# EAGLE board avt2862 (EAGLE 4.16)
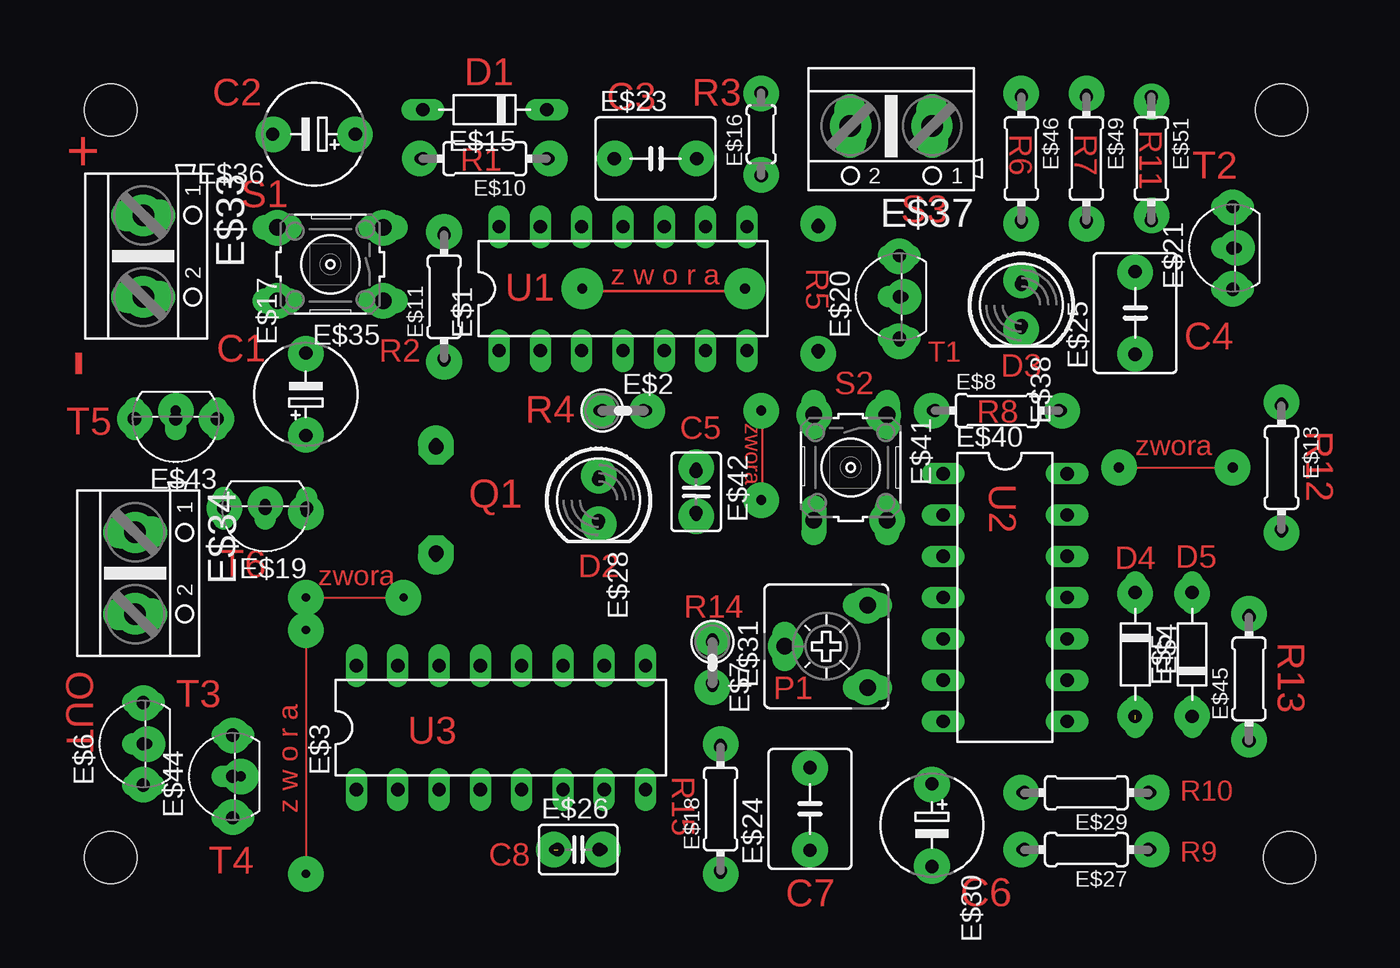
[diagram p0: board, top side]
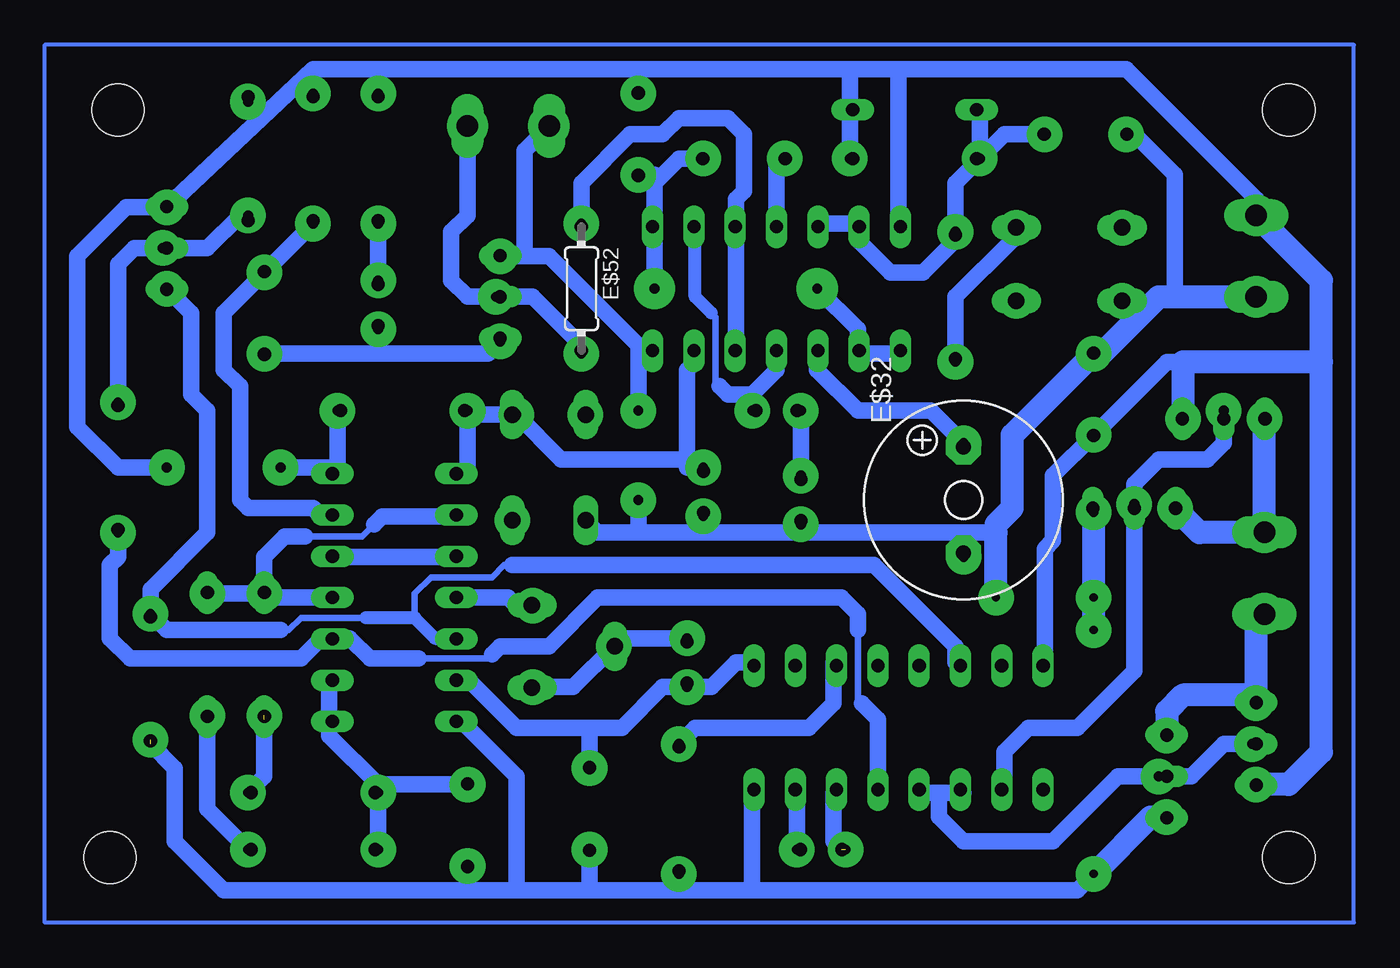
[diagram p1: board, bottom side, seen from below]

No outline drawn. Coordinates in mm, seen from the top.
Copper layers (1*16): Top 0.035mm / dielectric 1.5mm / Bottom 0.035mm
Design rules "default": minimum track width 10mil, minimum drill 24mil, track to track 8mil, track to pad 8mil, pad to pad 8mil, via to via 8mil, smd to smd 8mil, copper to edge 40mil, drill to drill 8mil, minimum pad ring 10mil, minimum via ring 8mil, stop-mask expansion 4mil, vias tented up to drill 0mil, thermal gap 10mil
Holes 3.2 mm at 0,54 0,8 72.5,8 72,54

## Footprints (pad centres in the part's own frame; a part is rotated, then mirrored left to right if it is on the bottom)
DIL14 = drill 0.813 long: 1 -7.62,-3.81; 2 -5.08,-3.81; 3 -2.54,-3.81; 4 0,-3.81; 5 2.54,-3.81; 6 5.08,-3.81; 7 7.62,-3.81; 8 7.62,3.81; 9 5.08,3.81; 10 2.54,3.81; 11 0,3.81; 12 -2.54,3.81; 13 -5.08,3.81; 14 -7.62,3.81
0207/2V = drill 0.813 octagon: 1 -1.27,0; 2 1.27,0
DIL16 = drill 0.813 long: 1 -8.89,-3.81; 2 -6.35,-3.81; 3 -3.81,-3.81; 4 -1.27,-3.81; 5 1.27,-3.81; 6 3.81,-3.81; 7 6.35,-3.81; 8 8.89,-3.81; 9 8.89,3.81; 10 6.35,3.81; 11 3.81,3.81; 12 1.27,3.81; 13 -1.27,3.81; 14 -3.81,3.81; 15 -6.35,3.81; 16 -8.89,3.81
D-7.5 = drill 0.813 long: A 3.81,0; C -3.81,0
TO92- = drill 0.813 long: 1 2.54,0; 2 0,0; 3 -2.54,0
0204/7 = drill 0.813 octagon: 1 -3.81,0; 2 3.81,0
0204/5 = drill 0.813 octagon: 1 -2.54,0; 2 2.54,0
E5-6 = drill 0.813 pad 1.905 round: + -2.54,0 | drill 0.813 pad 1.905 octagon: - 2.54,0
C050-050X075 = drill 0.813 octagon: 1 -2.54,0; 2 2.54,0
C025-030X050 = drill 0.813 octagon: 1 -1.27,0; 2 1.27,0
LED5MM = drill 0.813 octagon: A -1.27,0; K 1.27,0
CA6V = drill 1.016 long: A -2.54,-2.54; E 2.54,-2.54; S 0,2.54
F/QMX = drill 0.914 pad 2.159 octagon: + 3.251,0; - -3.251,0
AK500/2 = drill 1.321 long: 1 -2.515,0; 2 2.515,0
B3F-10XX = drill 1.016 long: 1 -3.251,2.261; 2 3.251,2.261; 3 -3.251,-2.261; 4 3.251,-2.261

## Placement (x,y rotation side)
E$1  [DIL14]  31.5,43 0 top
E$2  [0207/2V]  31.5,35.5 0 top
E$3  [DIL16]  24,16 0 top
E$4  [D-7.5]  63,20.5 270 top
E$5  [D-7.5]  66.5,20.5 90 top
E$6  [TO92-]  2,15 90 top
E$7  [0207/2V]  37,20 270 top
E$8  [0204/7]  54.5,35.5 0 top
E$10  [0204/7]  23,51 180 top
E$11  [0204/7]  20.5,42.5 90 top
E$13  [0204/7]  72,32 270 top
E$15  [D-7.5]  23,54 180 top
E$16  [0204/5]  40,52.5 90 top
E$17  [E5-6]  12,36.5 90 top
E$18  [0204/7]  37.5,11 90 top
E$19  [TO92-]  9.5,29.5 180 top
E$20  [TO92-]  48.5,42.5 90 top
E$21  [TO92-]  69,45.5 90 top
E$23  [C050-050X075]  33.5,51 0 top
E$24  [C050-050X075]  43,11 90 top
E$25  [C050-050X075]  63,41.5 90 top
E$26  [C025-030X050]  28.75,8.5 0 top
E$27  [0204/7]  60,8.5 180 top
E$28  [LED5MM]  30,30 270 top
E$29  [0204/7]  60,12 180 top
E$30  [E5-6]  50.5,10 270 top
E$31  [CA6V]  44,21 90 top
E$32  [F/QMX]  20,30 90 bottom
E$33  [AK500/2]  2,45 270 top
E$34  [AK500/2]  1.5,25.5 270 top
E$35  [B3F-10XX]  13.5,44.5 180 top
E$36  [E5-6]  12.5,52.5 180 top
E$37  [AK500/2]  48,53 180 top
E$38  [LED5MM]  56,42 270 top
E$40  [DIL14]  55,24 270 top
E$41  [B3F-10XX]  45.5,32 270 top
E$42  [C025-030X050]  36,30.5 270 top
E$43  [TO92-]  4,35 180 top
E$44  [TO92-]  7.5,13 90 top
E$45  [0204/7]  70,19 90 top
E$46  [0204/7]  56,51 270 top
E$49  [0204/7]  60,51 270 top
E$51  [0204/7]  64,51 270 top
E$52  [0204/7]  43.5,43 270 bottom

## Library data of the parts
E$1 E$3 E$40 = 40xx
E$2 E$7 E$8 E$10 E$11 E$13 E$16-E$18 E$23-E$27 E$29 E$30 E$36 E$42 E$45 E$46 E$49 E$51 E$52 = rcl
E$4 E$5 E$15 = diode
E$6 E$19-E$21 E$43 E$44 = transistor-npn
E$28 E$38 = led
E$31 = pot
E$32 = buzzer
E$33 E$34 E$37 = con-ptr500
E$35 E$41 = switch-omron

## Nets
S$79: E$19.2
S$95: E$6.2

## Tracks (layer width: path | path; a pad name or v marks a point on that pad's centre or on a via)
S$1
  Bottom 0.254: -4,4 76.5,4 76.5,58 -4,58 -4,4
S$2
  Bottom 1.422: 9.5,41.5 10,42
S$3  (via drill 0.6 pad 2.18)
  Bottom 1.016: v30,31.5 v30,35.5
S$4  (via drill 0.6 pad 2.18)
  Bottom 1.016: 17,47 17,46 20.5,42.5 v20.5,38.5
S$5
  Bottom 0.813: 36.5,47 36.5,42.5 35.5,41.5
S$6
  Bottom 1.016: 24,39 26.5,39
S$7
  Bottom 1.016: 59.5,21.5 57.75,21.5 56.5,20.25 53.5,20.25
S$8  (via drill 0.6 pad 2.18)
  other vias: 10.25,46.75
S$9  (via drill 0.6 pad 2.18)
  Bottom 1.016: 29,39 29,38 26.5,35.5 22,35.5 v20,33.5
S$10
  Bottom 1.016: 24,47 24,50.5
S$11  (via drill 0.6 pad 2.54)
  Bottom 1.016: 26.5,39.25 26.5,40.5 v29,43
S$12  (via drill 0.6 pad 2.18)
  Bottom 1.016: 31.5,47 31.5,50.5 v31,51
S$13  (via drill 0.6 pad 2.18)
  Bottom 1.016: 29,47 26.5,47 26.5,46 24.5,44 22.5,44 20.5,46 v20.5,46.5 20.5,49.5 v19,51 | v19,51 19,54 | v15,52.5 17.5,52.5 v19,51
S$14
  Bottom 0.406: 35.25,37 35.25,41.25
S$15  (via drill 0.6 pad 2.18, 0.6 pad 2.54)
  Bottom 1.016: v50.5,53 50.5,47.5 51.5,46.5 51.5,43.5 50.5,42.5 v48.75,42.5 46.5,42.5 43.5,39.5 v43.5,39
S$16  (via drill 0.6 pad 2.18)
  Bottom 1.016: 31.5,39 31.5,38 33,36.5 | 33,36.5 34.5,36.5 35,37 | v33,35.5 33,36.5
S$17  (via drill 0.6 pad 2.18)
  other vias: 20,26.5
S$18  (via drill 0.6 pad 2.18)
  Bottom 1.016: v43.5,47 43.5,49.5 40.5,52.5 38.5,52.5 37.5,53.5 34.5,53.5 33.5,52.5 33.5,49 34,48.5 34,39
S$19  (via drill 0.6 pad 2.18)
  Bottom 1.016: v56,43.5 v56,47
S$20  (via drill 0.6 pad 2.18)
  other vias: 8,13
S$21
  Bottom 1.016: 51,26.5 59,26.5
S$22
  Bottom 1.016: 20.5,20 20.5,21 25.5,26 47.75,26
S$23  (via drill 0.6 pad 2.18)
  Bottom 1.016: 58.5,29 59.5,29 60,29.5 64,29.5 64.5,30 64.5,37 65.5,38 65.5,41.5 v63,44 v60,47
S$24  (via drill 0.5 pad 2.18, 0.6 pad 2.18)  (1 unrouted)
  Bottom 1.016: 70,15 68.5,13.5 68.5,9 65.5,6 50.5,6 | 51,16.5 47.5,13 47.5,6 | 50.5,6 v50.5,7.5 | 47.5,6 50.5,6 | 43,6 v43,8.5 | 43,6 47.5,6 | 43,6 13,6 v12,7
  Bottom 1.422: v7.5,10.5 8.5,10.5 v12,7
  other vias: 70,15.25
S$25  (via drill 0.6 pad 2.18)
  Bottom 1.016: v37.5,15 36.5,16 35.5,16
S$26  (via drill 0.6 pad 2.18, 0.6 pad 2.54)
  Bottom 1.016: v45.5,53 47,51.5 47,45 | 47,45 45.5,45 40,39.5 | 47,45 v48.5,45 | 40,39.5 39,39.5 | v40,35.5 40,39.5
S$27  (via drill 0.6 pad 2.18)
  other vias: 10.25,42.25
S$28
  Bottom 0.406: 61.5,22 60.75,22.75 56.75,22.75
S$29  (via drill 0.6 pad 2.18)
  Bottom 1.016: 66.5,16.5 66.5,11 v64,8.5
S$30  (via drill 0.6 pad 2.18)
  Bottom 1.016: v56,8.5 56,12.5
S$31  (via drill 0.6 pad 2.18)  (1 unrouted)
  Bottom 1.016: 28,12 28,9 27.5,8.5
  other vias: 27.25,8.5
S$32  (via drill 0.6 pad 2.18)
  Bottom 1.016: v30.25,8.5 30.25,12.25
S$33  (via drill 0.6 pad 2.18)
  Bottom 1.016: 62,22 69,22 v70,23 70,24.5 66.5,28 66.5,35.5 67.5,36.5 67.5,41.5 v69,43
S$34
  Bottom 1.016: 35.5,16 29.5,16 28,17.5 28,20
S$35  (via drill 0.6 pad 2.18)
  Bottom 1.016: v50.5,12.5 56,12.5 59,15.5 59,19
S$36
  Bottom 1.016: 26.5,22 26.5,23 27.5,24 42.5,24 45.5,21 48.5,21 49,20.5
S$37  (via drill 0.6 pad 2.18)
  Bottom 1.016: 51,31.5 50.5,31.5 50.5,35.25 | 50.5,35.25 v50.5,35.5 | 50.5,35.25 v47.5,35.25 44.75,32.5 37.25,32.5 36.75,32 v36,32
S$38  (via drill 0.6 pad 2.18)
  Bottom 1.016: v37,21.5 41,21.5 v41.5,21 44,18.5 v46.5,18.5
S$39
  Bottom 1.016: 51,19 50.5,19 47.5,16 41,16 38.5,18.5 35.5,18.5 34,20 33,20
S$40  (via drill 0.6 pad 2.18)
  Bottom 1.016: 58.5,24 63,24 63,24.25 | 63,24.25 v66.5,24.25 | 60.5,27.75 61.75,27.75 63,26.5 63,24.25
S$41  (via drill 0.6 pad 2.18)
  Bottom 1.016: 56,39 v63,39 | 56,39 49.25,39 v48.5,39.75 | 56,39 v56,40.5
S$42
  Bottom 1.016: 36.5,39 36.5,38.5 37,38 37,32
S$43  (via drill 0.6 pad 2.18)
  Bottom 1.016: v43,13.5 43,16
S$44
  Bottom 0.406: 61.5,27.75 57,27.75 56.5,28.25
S$45  (via drill 0.6 pad 2.18)
  Bottom 1.016: 69,45.5 69.5,45.5 | 69,45.5 71,45.5 72,44.5 v72,36 | 69,45.5 66.5,45.5 64.5,47.5 v64,47.5
S$46
  Bottom 1.016: 33,6.5 33,12
S$47
  Bottom 0.406: 49,20.25 55.25,20.25
S$49  (via drill 0.6 pad 2.18)
  Bottom 1.016: 51.5,24 48,24 47.5,23.5 v46.5,23.5
S$50
  Bottom 0.406: 26.5,17.75 26.5,21.75
S$51  (via drill 0.6 pad 2.18)
  other vias: 66.5,16.75
S$52  (via drill 0.6 pad 2.18)
  other vias: 56,12
S$53
  Bottom 1.016: 51,29 55.75,29 56.25,28.5
S$54  (via drill 0.6 pad 2.18)
  Bottom 1.016: v40,50 39,50
S$55  (via drill 0.6 pad 2.18, 0.6 pad 2.54)
  Bottom 1.016: v39,43 39,49.5 37.5,51 v36,51
S$56  (via drill 0.6 pad 2.18, 0.6 pad 2.54)
  Bottom 1.016: v69,32 72,32 74.5,34.5 74.5,45 71.5,48 v69,48 60,56.5 | 60,56.5 v60,55 | 56,56.5 60,56.5 | 56,56.5 v56,55 | 27,56.5 56,56.5 | 27,56.5 v27,51 | 24,56.5 24,50.5 | 24,56.5 27,56.5 | 24,56.5 10,56.5 2,48.5 v2,47.5
  Bottom 1.422: v6.5,35 6.5,38.5 -2,38.5 | v2,47.5 -2,43.5 -2,38.5 | -2,38.5 -2,14.5 0,12.5 v2,12.5
S$60
  Bottom 1.016: 25.25,12.25 25.25,16.5 26.25,17.5
S$61  (via drill 0.6 pad 2.18)
  Bottom 1.016: v37.5,7 37.5,6.5
S$63  (via drill 0.6 pad 2.18)
  other vias: 43.25,35.25
S$64  (via drill 0.6 pad 2.18)
  other vias: 16.75,46.75
S$65
  Bottom 0.406: 53.75,22.75 53.75,24.25 52.75,25.25 49,25.25 48.25,26
  Bottom 0.813: 51,21.5 52.5,21.5 53.75,22.75 56.75,22.75
S$66  (via drill 0.6 pad 2.18)
  Bottom 1.016: 58.75,21.5 59.5,21.5 60.75,20.25 71.25,20.25 72.5,21.5 72.5,26 72,26.5 v72,28
S$67  (via drill 0.6 pad 2.18)
  Bottom 1.016: 58.5,32 v58.5,35.5 | 58.5,32 58.5,31.5 | 58.5,32 v62,32
S$68  (via drill 0.6 pad 2.18)
  Bottom 1.016: v64,54.5 63.5,54
S$69  (via drill 0.6 pad 2.18)
  other vias: 16.75,42.25
S$72  (via drill 0.6 pad 2.18)
  other vias: 69.25,45.5
S$75  (via drill 0.6 pad 2.18)
  Bottom 1.016: v36,29 36,28.5
S$76  (via drill 0.6 pad 2.18, 0.6 pad 2.54)
  Bottom 1.422: v2,17.5 2,18 | 2,18 2,22.5 v1.5,23 | v7.5,15.5 7.5,17 6.5,18 2,18
S$78  (via drill 0.6 pad 2.18)
  other vias: 37,18.5
S$79  (via drill 0.6 pad 2.18)
  Bottom 1.016: v4,35.5 4,33.5 5,32.5 8,32.5 9.5,31 v9.5,29.75 E$19.2 9.5,19.5 13,16 16,16 17.5,14.5 17.5,12
S$80  (via drill 0.6 pad 2.18)
  other vias: 47.75,28.75
S$83  (via drill 0.6 pad 2.18)  (1 unrouted)
  Bottom 1.016: 63,16.5 63,13 v64,12
  other vias: 63,16.75
S$84  (via drill 0.6 pad 2.18)
  other vias: 63,24.25
S$86  (via drill 0.6 pad 2.18)
  Bottom 1.016: 7,38.5 7.5,38.5 v12,34 14.5,31.5 14.5,27.5 15,27 15,19.5
S$89  (via drill 0.5 pad 2.18, 0.6 pad 2.18)
  Bottom 1.422: v12,22 v12,24 v12,29.25 12,29.5
S$90  (via drill 0.6 pad 2.18)
  Bottom 1.016: v10,52.5 9.5,52.5 7,50 7,42.5
S$91  (via drill 0.5 pad 2.18, 0.6 pad 2.18, 0.6 pad 2.54)
  Bottom 1.016: 18,28 20,28 | 20,28 30,28 | 30,28 40,28 | 40,28 42.5,28 43,28.5 | 40,28 v40,30 | 30,28 v30,28.5 | 20,28 20,26.5
  Bottom 1.422: v2,42.5 8,42.5 11.5,39 v12,39 17,34 17,29.5 18,28.5 18,28 v18,24
S$92  (via drill 0.6 pad 2.18)
  Bottom 1.016: v40,55 40,56
S$94  (via drill 0.6 pad 2.18, 0.6 pad 2.54)
  Bottom 1.422: v1.5,35 v1.5,28 5.5,28 v7,29.5
S$95  (via drill 0.6 pad 2.18)
  Bottom 1.016: 21.5,12 20,12 | 21.5,12 22.5,12 | E$6.2 v2.25,15 4,15 6,13 10.5,13 14.5,9 20,9 21.5,10.5 21.5,12

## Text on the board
Top: D1 | C2 | C3 | R3 | R11 | R6 | R7 | + | R1 | T2 | S3 | S1 | R5 | _______ | z w o r a | U1 | D3 | C4 | - | C1 | R2 | T1 | S2 | R4 | zwora | R8 | T5 | C5 | R12 | zwora | _______ | U2 | Q1 | ____ | D5 | D4 | T6 | zwora | D2 | ______ | R14 | R13 | OUT | P1 | T3 | U3 | R15 | R10 | z w o r a | C8 | R9 | T4 | _______________ | C7 | C6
